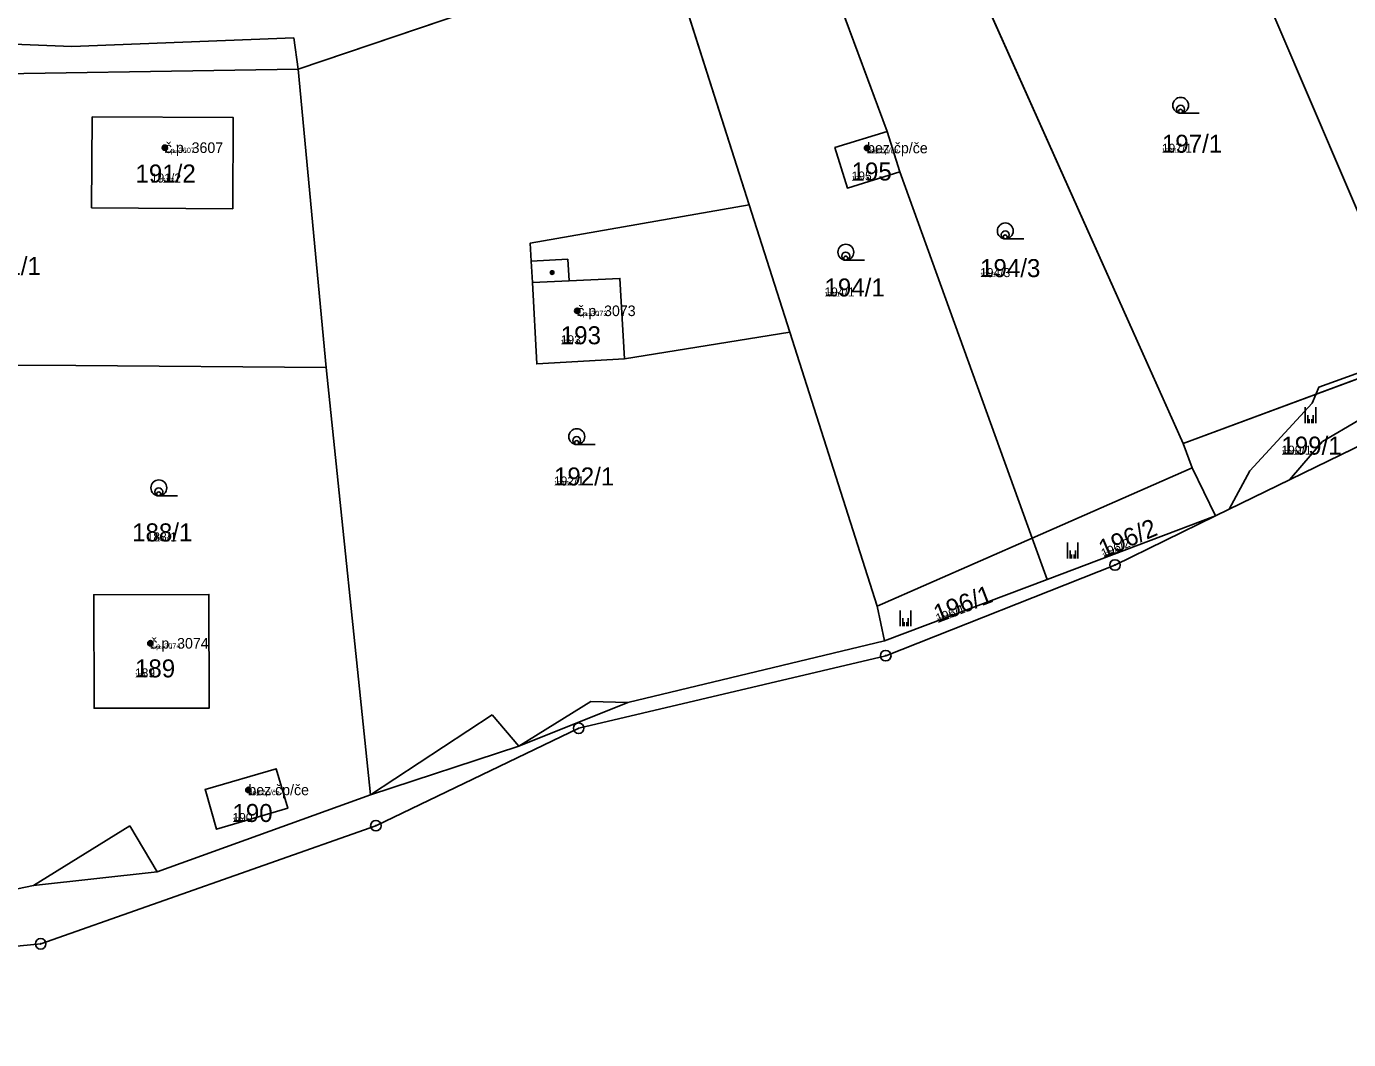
# Model space of a CAD drawing. Extents: x -759873 to -758487, y -975024 to -973516.
# Drawn here: x -759298.9 to -759174.1, y -974975.7 to -974880.1 of the extents above; entities that cross this region are included whole.
import ezdxf

# ---------------------------------------------------------------- set-up
doc = ezdxf.new("R2010")
doc.units = 0
for name, color, linetype in [('KAT_01_hranice KU', 7, 'Continuous'), ('KAT_02_hranice parcel', 7, 'Continuous'), ('KAT_03_1000_st čísla parcelní', 7, 'Continuous'), ('KAT_03_1000_čísla parcelní', 7, 'Continuous'), ('KAT_03_1000_čísla popisná', 7, 'Continuous'), ('KAT_03_250_st čísla parcelní', 7, 'Continuous'), ('KAT_03_250_čísla parcelní', 7, 'Continuous'), ('KAT_03_250_čísla popisná', 7, 'Continuous'), ('KAT_03_500_st čísla parcelní', 7, 'Continuous'), ('KAT_03_500_čísla parcelní', 7, 'Continuous'), ('KAT_03_500_čísla popisná', 7, 'Continuous'), ('KAT_04_vnitřní kresba', 7, 'Continuous'), ('KAT_05_1000_značky kultur', 7, 'Continuous'), ('KAT_05_250_značky kultur', 7, 'Continuous'), ('KAT_05_500_značky kultur', 7, 'Continuous'), ('KAT_07_1000_značky budov', 7, 'Continuous'), ('KAT_07_250_značky budov', 7, 'Continuous'), ('KAT_07_500_značky budov', 7, 'Continuous'), ('KAT_10_věcná břemena', 7, 'Continuous'), ('KAT_11_značky bodu BP', 7, 'Continuous'), ('KAT_14_plocha_budovy', 7, 'Continuous'), ('KAT_14_plocha_pozemek', 7, 'Continuous')]:
    doc.layers.add(name, color=color, linetype=linetype)

msp = doc.modelspace()

# ---------------------------------------------------------------- linework, layer by layer
at = {"layer": 'KAT_01_hranice KU'}
msp.add_lwpolyline([(-759474.45, -974968.85), (-759451.25, -974967.2), (-759419, -974971.89), (-759409.67, -974973.58), (-759397.92, -974975.71), (-759368.31, -974972.47), (-759365.9, -974972.21), (-759314.5, -974968.3), (-759297.56, -974966.67), (-759265.92, -974955.52), (-759246.78, -974946.32), (-759217.8, -974939.47), (-759196.16, -974930.91), (-759186.66, -974926.27), (-759165.4, -974915.9)], dxfattribs=at)
at = {"layer": 'KAT_02_hranice parcel'}
for p, q in [((-759167.42, -974911.17), (-759194.44, -974847.98)), ((-759189.72, -974919.43), (-759216.19, -974860.33)), ((-759217.66, -974889.98), (-759226.6, -974865.92)), ((-759238.51, -974872.32), (-759273.27, -974884.11)), ((-759230.68, -974896.92), (-759238.51, -974872.32)), ((-759270.6, -974912.26), (-759273.27, -974884.11)), ((-759217.66, -974889.98), (-759216.48, -974893.8)), ((-759203.97, -974928.37), (-759216.48, -974893.8)), ((-759226.86, -974908.93), (-759230.68, -974896.92)), ((-759218.62, -974934.8), (-759226.86, -974908.93)), ((-759189.72, -974919.43), (-759167.42, -974911.17)), ((-759270.6, -974912.26), (-759266.42, -974952.62)), ((-759186.66, -974926.27), (-759165.4, -974915.9)), ((-759188.86, -974921.74), (-759189.72, -974919.43)), ((-759203.97, -974928.37), (-759188.86, -974921.74)), ((-759186.66, -974926.27), (-759188.86, -974921.74)), ((-759186.66, -974926.27), (-759202.56, -974932.28)), ((-759218.62, -974934.8), (-759203.97, -974928.37)), ((-759202.56, -974932.28), (-759203.97, -974928.37)), ((-759202.56, -974932.28), (-759217.9, -974938.08)), ((-759217.9, -974938.08), (-759218.62, -974934.8)), ((-759246.78, -974946.32), (-759217.8, -974939.47))]:
    msp.add_line(p, q, dxfattribs=at)
for points in [[(-759273.27, -974884.11), (-759273.68, -974881.15), (-759294.63, -974881.97), (-759309.62, -974881.37), (-759315.34, -974883.88)], [(-759273.27, -974884.11), (-759309.11, -974884.68), (-759315.57, -974899.46)], [(-759292.75, -974897.18), (-759292.69, -974888.6), (-759279.39, -974888.67), (-759279.43, -974897.27), (-759292.75, -974897.18)], [(-759216.48, -974893.8), (-759221.42, -974895.32), (-759222.6, -974891.5), (-759217.66, -974889.98)], [(-759226.86, -974908.93), (-759242.46, -974911.45), (-759250.73, -974911.92), (-759251.15, -974904.23), (-759251.27, -974902.24), (-759251.36, -974900.54), (-759230.68, -974896.92)], [(-759300.82, -974912.03), (-759294.25, -974912.08), (-759270.6, -974912.26)], [(-759217.8, -974939.47), (-759196.16, -974930.91), (-759186.66, -974926.27)], [(-759281.65, -974944.41), (-759281.68, -974933.68), (-759292.55, -974933.72), (-759292.52, -974944.44), (-759281.65, -974944.41)], [(-759217.9, -974938.08), (-759242.15, -974943.89), (-759252.42, -974948.01), (-759266.42, -974952.62)], [(-759314.5, -974968.3), (-759297.56, -974966.67), (-759265.92, -974955.52), (-759246.78, -974946.32)], [(-759281.98, -974952.28), (-759280.97, -974955.86), (-759274.24, -974953.88), (-759275.33, -974950.14), (-759282.04, -974952.09), (-759281.98, -974952.28)], [(-759266.42, -974952.62), (-759286.56, -974959.86), (-759298.23, -974961.16), (-759302.97, -974962.15)]]:
    msp.add_lwpolyline(points, dxfattribs=at)
at = {"layer": 'KAT_03_1000_čísla popisná'}
for centre in [(-759285.84, -974891.51), (-759219.56, -974891.54), (-759246.91, -974906.91), (-759287.21, -974938.3), (-759277.96, -974952.14)]:
    msp.add_circle(centre, 0.25, dxfattribs=at)
at = {"layer": 'KAT_03_250_čísla popisná'}
for centre in [(-759285.84, -974891.51), (-759219.56, -974891.54), (-759246.91, -974906.91), (-759287.21, -974938.3), (-759277.96, -974952.14)]:
    msp.add_circle(centre, 0.0625, dxfattribs=at)
at = {"layer": 'KAT_03_500_čísla popisná'}
for centre in [(-759285.84, -974891.51), (-759219.56, -974891.54), (-759246.91, -974906.91), (-759287.21, -974938.3), (-759277.96, -974952.14)]:
    msp.add_circle(centre, 0.125, dxfattribs=at)
at = {"layer": 'KAT_04_vnitřní kresba'}
for p, q in [((-759251.27, -974902.24), (-759247.79, -974902.04)), ((-759247.79, -974902.04), (-759247.68, -974904.08)), ((-759251.15, -974904.23), (-759247.68, -974904.08)), ((-759247.68, -974904.08), (-759242.88, -974903.86)), ((-759242.88, -974903.86), (-759242.46, -974911.45)), ((-759252.42, -974948.01), (-759245.63, -974943.78)), ((-759245.63, -974943.78), (-759242.15, -974943.89)), ((-759266.42, -974952.62), (-759254.96, -974945.06)), ((-759254.96, -974945.06), (-759252.42, -974948.01)), ((-759298.23, -974961.16), (-759289.15, -974955.52)), ((-759289.15, -974955.52), (-759286.56, -974959.86))]:
    msp.add_line(p, q, dxfattribs=at)
at = {"layer": 'KAT_05_1000_značky kultur'}
for p, q in [((-759189.96, -974888.26), (-759188.21, -974888.26)), ((-759206.51, -974900.12), (-759204.76, -974900.12)), ((-759221.56, -974902.13), (-759219.81, -974902.13)), ((-759178.21, -974917.52), (-759178.21, -974916.02)), ((-759177.21, -974917.52), (-759177.21, -974916.02)), ((-759246.96, -974919.54), (-759245.21, -974919.54)), ((-759286.41, -974924.38), (-759284.66, -974924.38)), ((-759200.65, -974930.3), (-759200.65, -974928.8)), ((-759199.65, -974930.3), (-759199.65, -974928.8)), ((-759216.43, -974936.69), (-759216.43, -974935.19)), ((-759215.43, -974936.69), (-759215.43, -974935.19))]:
    msp.add_line(p, q, dxfattribs=at)
for centre in [(-759189.96, -974887.51), (-759206.51, -974899.37), (-759221.56, -974901.38), (-759246.96, -974918.79), (-759286.41, -974923.63)]:
    msp.add_circle(centre, 0.75, dxfattribs=at)
at = {"layer": 'KAT_05_250_značky kultur'}
for p, q in [((-759189.97, -974888.26), (-759189.53, -974888.26)), ((-759206.52, -974900.12), (-759206.08, -974900.12)), ((-759221.57, -974902.13), (-759221.13, -974902.13)), ((-759177.83, -974917.52), (-759177.83, -974917.15)), ((-759177.58, -974917.52), (-759177.58, -974917.15)), ((-759246.97, -974919.54), (-759246.53, -974919.54)), ((-759286.42, -974924.38), (-759285.98, -974924.38)), ((-759200.27, -974930.3), (-759200.27, -974929.93)), ((-759200.02, -974930.3), (-759200.02, -974929.93)), ((-759216.05, -974936.69), (-759216.05, -974936.32)), ((-759215.8, -974936.69), (-759215.8, -974936.32))]:
    msp.add_line(p, q, dxfattribs=at)
for centre in [(-759189.97, -974888.07), (-759206.52, -974899.93), (-759221.57, -974901.94), (-759246.97, -974919.35), (-759286.42, -974924.19)]:
    msp.add_circle(centre, 0.187, dxfattribs=at)
at = {"layer": 'KAT_05_500_značky kultur'}
for p, q in [((-759189.97, -974888.26), (-759189.09, -974888.26)), ((-759206.52, -974900.12), (-759205.64, -974900.12)), ((-759221.57, -974902.13), (-759220.69, -974902.13)), ((-759177.96, -974917.52), (-759177.96, -974916.77)), ((-759177.45, -974917.52), (-759177.45, -974916.77)), ((-759246.97, -974919.54), (-759246.09, -974919.54)), ((-759286.42, -974924.38), (-759285.54, -974924.38)), ((-759200.4, -974930.3), (-759200.4, -974929.55)), ((-759199.9, -974930.3), (-759199.9, -974929.55)), ((-759216.18, -974936.69), (-759216.18, -974935.94)), ((-759215.68, -974936.69), (-759215.68, -974935.94))]:
    msp.add_line(p, q, dxfattribs=at)
for centre in [(-759189.97, -974887.88), (-759206.52, -974899.74), (-759221.57, -974901.75), (-759246.97, -974919.16), (-759286.42, -974924)]:
    msp.add_circle(centre, 0.375, dxfattribs=at)
at = {"layer": 'KAT_07_1000_značky budov'}
for centre in [(-759285.85, -974891.51), (-759219.57, -974891.54), (-759249.29, -974903.3), (-759246.92, -974906.91), (-759287.22, -974938.3), (-759277.97, -974952.14)]:
    msp.add_circle(centre, 0.175, dxfattribs=at)
at = {"layer": 'KAT_07_250_značky budov'}
for centre in [(-759285.84, -974891.51), (-759219.56, -974891.54), (-759249.28, -974903.3), (-759246.91, -974906.91), (-759287.21, -974938.3), (-759277.96, -974952.14)]:
    msp.add_circle(centre, 0.0437, dxfattribs=at)
at = {"layer": 'KAT_07_500_značky budov'}
for centre in [(-759285.84, -974891.51), (-759219.56, -974891.54), (-759249.28, -974903.3), (-759246.91, -974906.91), (-759287.21, -974938.3), (-759277.96, -974952.14)]:
    msp.add_circle(centre, 0.0875, dxfattribs=at)
at = {"layer": 'KAT_10_věcná břemena'}
msp.add_lwpolyline([(-759185.38, -974925.65), (-759179.69, -974922.87), (-759176.57, -974919.25), (-759169.71, -974915.21), (-759166.93, -974912.32), (-759167.42, -974911.17), (-759170.55, -974903.85), (-759172.36, -974910.31), (-759172.64, -974912.59), (-759176.92, -974914.13), (-759177.21, -974914.8), (-759177.56, -974915.62), (-759183.42, -974922.02)], close=True, dxfattribs=at)
at = {"layer": 'KAT_11_značky bodu BP'}
for centre, radius in [((-759196.16, -974930.91), 0.5), ((-759196.16, -974930.91), 0.0303), ((-759217.8, -974939.47), 0.5), ((-759217.8, -974939.47), 0.0303), ((-759246.78, -974946.32), 0.5), ((-759246.78, -974946.32), 0.0303), ((-759265.92, -974955.52), 0.5), ((-759265.92, -974955.52), 0.0303), ((-759297.56, -974966.67), 0.5), ((-759297.56, -974966.67), 0.0303)]:
    msp.add_circle(centre, radius, dxfattribs=at)
at = {"layer": 'KAT_14_plocha_budovy'}
for points in [[(-759292.69, -974888.6), (-759292.75, -974897.18), (-759279.43, -974897.27), (-759279.39, -974888.67)], [(-759217.66, -974889.98), (-759222.6, -974891.5), (-759221.42, -974895.32), (-759216.48, -974893.8)], [(-759247.68, -974904.08), (-759251.15, -974904.23), (-759250.73, -974911.92), (-759242.46, -974911.45), (-759242.88, -974903.86)], [(-759292.55, -974933.72), (-759292.52, -974944.44), (-759281.65, -974944.41), (-759281.68, -974933.68)], [(-759275.33, -974950.14), (-759282.04, -974952.09), (-759281.98, -974952.28), (-759280.97, -974955.86), (-759274.24, -974953.88)]]:
    msp.add_lwpolyline(points, close=True, dxfattribs=at)
at = {"layer": 'KAT_14_plocha_pozemek'}
for points in [[(-759309.62, -974881.37), (-759294.63, -974881.97), (-759273.68, -974881.15), (-759273.27, -974884.11), (-759238.51, -974872.32), (-759226.6, -974865.92), (-759216.19, -974860.33), (-759216.36, -974859.96), (-759214.86, -974859.41), (-759208.68, -974856.28), (-759196.21, -974843.87), (-759187.6, -974835.12), (-759186.16, -974833.19), (-759188.78, -974830.26), (-759199.03, -974838.5), (-759208.71, -974845.67), (-759206.61, -974849.33), (-759220.29, -974856.48), (-759236.4, -974863.83), (-759249.2, -974869.3), (-759260.46, -974873.03), (-759275.76, -974876.39), (-759289.39, -974877.59), (-759306.31, -974877.26)], [(-759314.5, -974968.3), (-759297.56, -974966.67), (-759265.92, -974955.52), (-759246.78, -974946.32), (-759217.8, -974939.47), (-759196.16, -974930.91), (-759186.66, -974926.27), (-759202.56, -974932.28), (-759217.9, -974938.08), (-759242.15, -974943.89), (-759252.42, -974948.01), (-759266.42, -974952.62), (-759286.56, -974959.86), (-759298.23, -974961.16), (-759302.97, -974962.15)]]:
    msp.add_lwpolyline(points, dxfattribs=at)
for points in [[(-759178.07, -974834.41), (-759176.83, -974838.48), (-759182.55, -974840.22), (-759183.12, -974838.42), (-759194.44, -974847.98), (-759167.42, -974911.17), (-759145.92, -974903.21), (-759159.23, -974872.41), (-759176.11, -974832.51), (-759176.83, -974833.12), (-759178.53, -974834.55)], [(-759194.44, -974847.98), (-759200.21, -974852.85), (-759216.19, -974860.33), (-759189.72, -974919.43), (-759167.42, -974911.17)], [(-759216.19, -974860.33), (-759226.6, -974865.92), (-759217.66, -974889.98), (-759216.48, -974893.8), (-759203.97, -974928.37), (-759188.86, -974921.74), (-759189.72, -974919.43)], [(-759226.6, -974865.92), (-759238.51, -974872.32), (-759230.68, -974896.92), (-759226.86, -974908.93), (-759218.62, -974934.8), (-759203.97, -974928.37), (-759216.48, -974893.8), (-759221.42, -974895.32), (-759222.6, -974891.5), (-759217.66, -974889.98)], [(-759238.51, -974872.32), (-759273.27, -974884.11), (-759270.6, -974912.26), (-759266.42, -974952.62), (-759252.42, -974948.01), (-759242.15, -974943.89), (-759217.9, -974938.08), (-759218.62, -974934.8), (-759226.86, -974908.93), (-759242.46, -974911.45), (-759250.73, -974911.92), (-759251.15, -974904.23), (-759251.27, -974902.24), (-759251.36, -974900.54), (-759230.68, -974896.92)], [(-759273.27, -974884.11), (-759273.68, -974881.15), (-759294.63, -974881.97), (-759309.62, -974881.37), (-759315.34, -974883.88), (-759315.5, -974887.66), (-759315.85, -974899.09), (-759315.57, -974899.46), (-759309.11, -974884.68)], [(-759318.3, -974904.94), (-759318.19, -974911.9), (-759300.82, -974912.03), (-759294.25, -974912.08), (-759270.6, -974912.26), (-759273.27, -974884.11), (-759309.11, -974884.68), (-759315.57, -974899.46)], [(-759292.75, -974897.18), (-759292.69, -974888.6), (-759279.39, -974888.67), (-759279.43, -974897.27)], [(-759292.75, -974897.18), (-759279.43, -974897.27), (-759279.39, -974888.67), (-759292.69, -974888.6)], [(-759217.66, -974889.98), (-759222.6, -974891.5), (-759221.42, -974895.32), (-759216.48, -974893.8)], [(-759226.86, -974908.93), (-759230.68, -974896.92), (-759251.36, -974900.54), (-759251.27, -974902.24), (-759251.15, -974904.23), (-759250.73, -974911.92), (-759242.46, -974911.45)], [(-759300.82, -974912.03), (-759302.97, -974962.15), (-759298.23, -974961.16), (-759286.56, -974959.86), (-759266.42, -974952.62), (-759270.6, -974912.26), (-759294.25, -974912.08)], [(-759165.4, -974915.9), (-759167.42, -974911.17), (-759189.72, -974919.43), (-759188.86, -974921.74), (-759186.66, -974926.27)], [(-759186.66, -974926.27), (-759188.86, -974921.74), (-759203.97, -974928.37), (-759202.56, -974932.28)], [(-759202.56, -974932.28), (-759203.97, -974928.37), (-759218.62, -974934.8), (-759217.9, -974938.08)], [(-759281.65, -974944.41), (-759281.68, -974933.68), (-759292.55, -974933.72), (-759292.52, -974944.44)], [(-759281.65, -974944.41), (-759292.52, -974944.44), (-759292.55, -974933.72), (-759281.68, -974933.68)], [(-759281.98, -974952.28), (-759280.97, -974955.86), (-759274.24, -974953.88), (-759275.33, -974950.14), (-759282.04, -974952.09)], [(-759281.98, -974952.28), (-759282.04, -974952.09), (-759275.33, -974950.14), (-759274.24, -974953.88), (-759280.97, -974955.86)]]:
    msp.add_lwpolyline(points, close=True, dxfattribs=at)

# ---------------------------------------------------------------- texts
at = {"layer": 'KAT_03_1000_st čísla parcelní'}
for s, p in [('191/2', (-759288.61, -974894.8)), ('195', (-759221.02, -974894.61)), ('193', (-759248.47, -974910.07)), ('189', (-759288.66, -974941.52)), ('190', (-759279.46, -974955.17))]:
    msp.add_text(s, height=1.7, dxfattribs=at).set_placement(p)
at = {"layer": 'KAT_03_1000_čísla parcelní'}
for s, p in [('197/1', (-759191.73, -974891.99)), ('191/1', (-759303.23, -974903.53)), ('194/3', (-759208.89, -974903.73)), ('194/1', (-759223.58, -974905.56)), ('199/1', (-759180.45, -974920.49)), ('192/1', (-759249.11, -974923.4)), ('188/1', (-759288.93, -974928.68))]:
    msp.add_text(s, height=1.7, dxfattribs=at).set_placement(p)
for s, rotation, p in [('196/2', 23, (-759197.25, -974930.26)), ('196/1', 21, (-759212.88, -974936.39))]:
    msp.add_text(s, height=1.7, rotation=rotation, dxfattribs=at).set_placement(p)
at = {"layer": 'KAT_03_1000_čísla popisná'}
for s, p in [('č.p. 3607', (-759285.84, -974892.01)), ('bez čp/če', (-759219.56, -974892.04)), ('č.p. 3073', (-759246.91, -974907.41)), ('č.p. 3074', (-759287.21, -974938.8)), ('bez čp/če', (-759277.96, -974952.64))]:
    msp.add_text(s, height=1, dxfattribs=at).set_placement(p)
at = {"layer": 'KAT_03_250_st čísla parcelní'}
for s, p in [('191/2', (-759286.43, -974894.8)), ('195', (-759221.02, -974894.61)), ('193', (-759248.47, -974910.07)), ('189', (-759288.66, -974941.52)), ('190', (-759279.46, -974955.17))]:
    msp.add_text(s, height=0.425, dxfattribs=at).set_placement(p)
at = {"layer": 'KAT_03_250_čísla parcelní'}
for s, p in [('197/1', (-759191.73, -974891.99)), ('194/3', (-759208.89, -974903.73)), ('194/1', (-759223.58, -974905.56)), ('199/1', (-759180.45, -974920.49)), ('192/1', (-759249.11, -974923.4)), ('188/1', (-759286.87, -974928.68))]:
    msp.add_text(s, height=0.425, dxfattribs=at).set_placement(p)
for s, rotation, p in [('196/2', 23, (-759197.25, -974930.26)), ('196/1', 21, (-759212.88, -974936.39))]:
    msp.add_text(s, height=0.425, rotation=rotation, dxfattribs=at).set_placement(p)
at = {"layer": 'KAT_03_250_čísla popisná'}
for s, p in [('č.p. 3607', (-759285.84, -974892.01)), ('bez čp/če', (-759219.56, -974892.04)), ('č.p. 3073', (-759246.91, -974907.41)), ('č.p. 3074', (-759287.21, -974938.8)), ('bez čp/če', (-759277.96, -974952.64))]:
    msp.add_text(s, height=0.25, dxfattribs=at).set_placement(p)
at = {"layer": 'KAT_03_500_st čísla parcelní'}
for s, p in [('191/2', (-759287.16, -974894.8)), ('195', (-759221.02, -974894.61)), ('193', (-759248.47, -974910.07)), ('189', (-759288.66, -974941.52)), ('190', (-759279.46, -974955.17))]:
    msp.add_text(s, height=0.85, dxfattribs=at).set_placement(p)
at = {"layer": 'KAT_03_500_čísla parcelní'}
for s, p in [('197/1', (-759191.73, -974891.99)), ('194/3', (-759208.89, -974903.73)), ('194/1', (-759223.58, -974905.56)), ('199/1', (-759180.45, -974920.49)), ('192/1', (-759249.11, -974923.4)), ('188/1', (-759287.56, -974928.68))]:
    msp.add_text(s, height=0.85, dxfattribs=at).set_placement(p)
for s, rotation, p in [('196/2', 23, (-759197.25, -974930.26)), ('196/1', 21, (-759212.88, -974936.39))]:
    msp.add_text(s, height=0.85, rotation=rotation, dxfattribs=at).set_placement(p)
at = {"layer": 'KAT_03_500_čísla popisná'}
for s, p in [('č.p. 3607', (-759285.84, -974892.01)), ('bez čp/če', (-759219.56, -974892.04)), ('č.p. 3073', (-759246.91, -974907.41)), ('č.p. 3074', (-759287.21, -974938.8)), ('bez čp/če', (-759277.96, -974952.64))]:
    msp.add_text(s, height=0.5, dxfattribs=at).set_placement(p)

doc.saveas('drawing.dxf')
